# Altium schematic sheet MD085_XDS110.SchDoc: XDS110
size 431 x 279 mm; Date: Not shown in title block; ApprovedBy: Not shown in title block; CheckedBy: Not shown in title block; Author: Not shown in title block; CompanyName: Not shown in title block; DrawnBy: Keerthi Kumanan; Engineer: Not shown in title block; Organization: Not shown in title block; Address1: Not shown in title block; Address2: Not shown in title block; Address3: Not shown in title block; Address4: Not shown in title block; DocumentNumber: 2; Revision: Use project parameter SCH_Rev; SheetNumber: 2; SheetTotal: 2; PageSetup: Record=PageOptions¦CenterHorizontal=True¦CenterVertical=True¦PrintScale=1.00¦XCorrection=1.00¦YCorrection=1.00¦PrintKind=0¦BorderSize=5000000¦LeftOffset=0¦BottomOffset=0¦Orientation=2¦PaperLength=1000¦PaperWidth=1000¦Scale=100¦PaperSource=15¦PrintQuality=600¦MediaType=1¦DitherType=10¦PaperKind=Letter¦PrintScaleMode=1
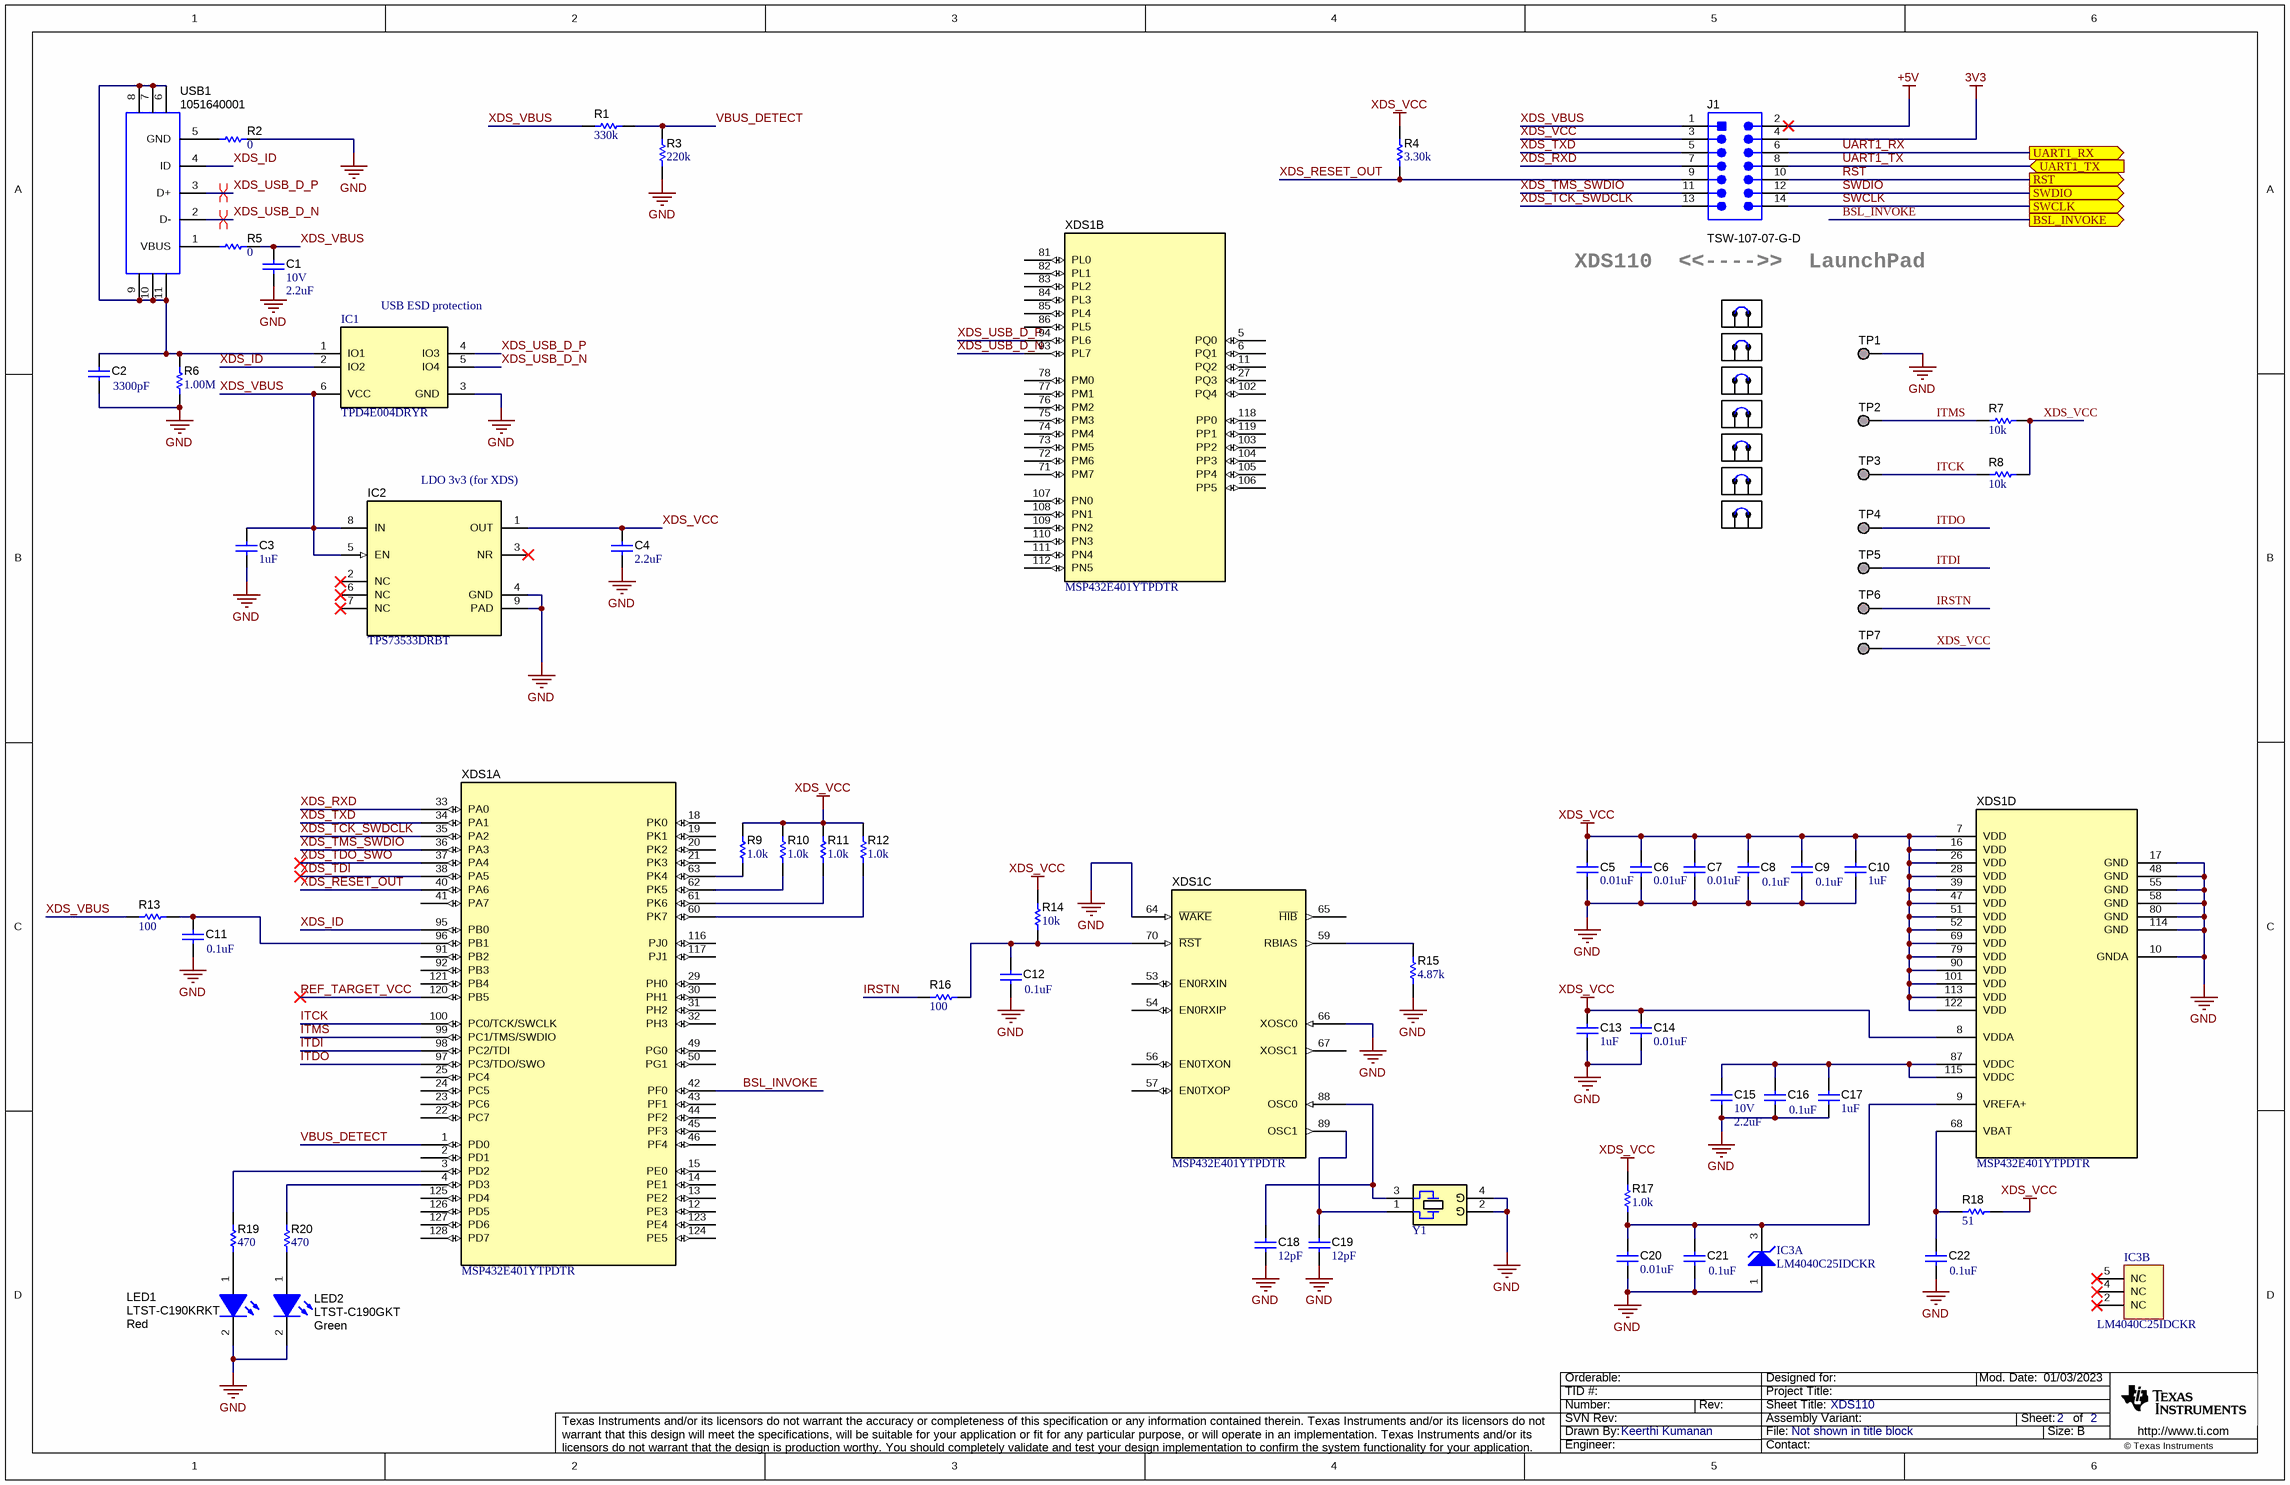
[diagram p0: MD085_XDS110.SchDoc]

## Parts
C1  VDC_V: 10V  ValueDisplayed: 2.2uF  [0603]  (hidden comment: C0603C225K8PACTU)
C2  ValueDisplayed: 3300pF  [0402]  (hidden comment: GRM155R71H332KA01D)
C3  ValueDisplayed: 1uF  [0402]  (hidden comment: C1005X5R1E105K050BC)
C4  ValueDisplayed: 2.2uF  [0402]  (hidden comment: CL05A225KQ5NNNC)
C5  ValueDisplayed: 0.01uF  [0402]  (hidden comment: GRM155R71E103KA01D)
C6  ValueDisplayed: 0.01uF  [0402]  (hidden comment: GRM155R71E103KA01D)
C7  ValueDisplayed: 0.01uF  [0402]  (hidden comment: GRM155R71E103KA01D)
C8  ValueDisplayed: 0.1uF  [0402]  (hidden comment: GRM155R70J104KA01D)
C9  ValueDisplayed: 0.1uF  [0402]  (hidden comment: GRM155R70J104KA01D)
C10  ValueDisplayed: 1uF  [0402]  (hidden comment: C1005X5R1E105K050BC)
C11  ValueDisplayed: 0.1uF  [0402]  (hidden comment: GRM155R70J104KA01D)
C12  ValueDisplayed: 0.1uF  [0402]  (hidden comment: GRM155R70J104KA01D)
C13  ValueDisplayed: 1uF  [0402]  (hidden comment: C1005X5R1E105K050BC)
C14  ValueDisplayed: 0.01uF  [0402]  (hidden comment: GRM155R71E103KA01D)
C15  VDC_V: 10V  ValueDisplayed: 2.2uF  [0603]  (hidden comment: C0603C225K8PACTU)
C16  ValueDisplayed: 0.1uF  [0402]  (hidden comment: GRM155R70J104KA01D)
C17  ValueDisplayed: 1uF  [0402]  (hidden comment: C1005X5R1E105K050BC)
C18  ValueDisplayed: 12pF  [0402]  (hidden comment: GRM1555C1H120JA01D)
C19  ValueDisplayed: 12pF  [0402]  (hidden comment: GRM1555C1H120JA01D)
C20  ValueDisplayed: 0.01uF  [0402]  (hidden comment: GRM155R71E103KA01D)
C21  ValueDisplayed: 0.1uF  [0402]  (hidden comment: GRM155R70J104KA01D)
C22  ValueDisplayed: 0.1uF  [0402]  (hidden comment: GRM155R70J104KA01D)
IC1  TPD4E004DRYR  [DRY0006A]
IC2  TPS73533DRBT  [DRB0008A]
IC3  LM4040C25IDCKR  [DCK0005A_N]  (parts A,B of 2)
J1  TSW-107-07-G-D  [TSW-107-07-X-D]
LED1  LTST-C190KRKT  value Red  [LED_LTST-C190_Red]
LED2  LTST-C190GKT  value Green  [LED_LTST-C190]
R1  ValueDisplayed: 330k  [0402]  (hidden comment: RC0402FR-07330KL)
R2  ValueDisplayed: 0  [0603]  (hidden comment: RC0603JR-070RL)
R3  ValueDisplayed: 220k  [0402]  (hidden comment: RC0402FR-07220KL)
R4  ValueDisplayed: 3.30k  [0402]  (hidden comment: ERJ-2RKF3301X)
R5  ValueDisplayed: 0  [0603]  (hidden comment: RC0603JR-070RL)
R6  ValueDisplayed: 1.00M  [0402]  (hidden comment: CRCW04021M00FKED)
R7  ValueDisplayed: 10k  [0402]  (hidden comment: CRCW040210K0JNED)
R8  ValueDisplayed: 10k  [0402]  (hidden comment: CRCW040210K0JNED)
R9  ValueDisplayed: 1.0k  [0402]  (hidden comment: CRCW04021K00JNED)
R10  ValueDisplayed: 1.0k  [0402]  (hidden comment: CRCW04021K00JNED)
R11  ValueDisplayed: 1.0k  [0402]  (hidden comment: CRCW04021K00JNED)
R12  ValueDisplayed: 1.0k  [0402]  (hidden comment: CRCW04021K00JNED)
R13  ValueDisplayed: 100  [0402]  (hidden comment: CRCW0402100RJNED)
R14  ValueDisplayed: 10k  [0402]  (hidden comment: CRCW040210K0JNED)
R15  ValueDisplayed: 4.87k  [0402]  (hidden comment: CRCW04024K87FKED)
R16  ValueDisplayed: 100  [0402]  (hidden comment: CRCW0402100RJNED)
R17  ValueDisplayed: 1.0k  [0402]  (hidden comment: CRCW04021K00JNED)
R18  ValueDisplayed: 51  [0402]  (hidden comment: CRCW040251R0JNED)
R19  ValueDisplayed: 470  [0402]  (hidden comment: CRCW0402470RJNED)
R20  ValueDisplayed: 470  [0402]  (hidden comment: CRCW0402470RJNED)
SH-J14  60900213421  [Wurth_60900213421]  (value not drawn)
SH-J15  60900213421  [Wurth_60900213421]  (value not drawn)
SH-J16  60900213421  [Wurth_60900213421]  (value not drawn)
SH-J17  60900213421  [Wurth_60900213421]  (value not drawn)
SH-J18  60900213421  [Wurth_60900213421]  (value not drawn)
SH-J19  60900213421  [Wurth_60900213421]  (value not drawn)
SH-J20  60900213421  [Wurth_60900213421]  (value not drawn)
TP1  TESTPOINT  [TP_SM_1MM]  (value not drawn)  (no BOM)
TP2  TESTPOINT  [TP_SM_1MM]  (value not drawn)  (no BOM)
TP3  TESTPOINT  [TP_SM_1MM]  (value not drawn)  (no BOM)
TP4  TESTPOINT  [TP_SM_1MM]  (value not drawn)  (no BOM)
TP5  TESTPOINT  [TP_SM_1MM]  (value not drawn)  (no BOM)
TP6  TESTPOINT  [TP_SM_1MM]  (value not drawn)  (no BOM)
TP7  TESTPOINT  [TP_SM_1MM]  (value not drawn)  (no BOM)
USB1  1051640001  [Molex_1051640001]
XDS1  MSP432E401YTPDTR  [PDT0128A]  (parts A,B,C,D of 4)
Y1  NX3225GA-16.000M-STD-CRG-1  [NDK_NX3225GA]  (value not drawn)

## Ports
BSL_INVOKE (out), RST (out), SWCLK (out), SWDIO (out), UART1_RX (out), UART1_TX (in)

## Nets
3V3: J1.4
+5V: J1.2
GND: C1.2 C2.2 C3.2 C4.2 C5.2 C6.2 C7.2 C8.2 C9.2 C10.2 C11.2 C12.2 C13.2 C14.2 C15.2 C16.2 C17.2 C18.2 C19.2 C20.2 C21.2 C22.2 IC1.3(GND) IC2.4(GND) IC2.9(PAD) IC3.1(ANODE) LED1.2(K) LED2.2(K) R2.2 R3.1 R6.1 R15.1 TP1.1 XDS1.10(GNDA) XDS1.17(GND) XDS1.48(GND) XDS1.55(GND) XDS1.58(GND) XDS1.64(~{WAKE}) XDS1.66(XOSC0) XDS1.80(GND) XDS1.114(GND) Y1.2(GND) Y1.4(GND)
XDS_VCC: C4.1 C5.1 C6.1 C7.1 C8.1 C9.1 C10.1 C13.1 C14.1 IC2.1(OUT) J1.3 R4.2 R7.1 R8.1 R9.2 R10.2 R11.2 R12.2 R14.2 R17.2 R18.2 TP7.1 XDS1.7(VDD) XDS1.8(VDDA) XDS1.16(VDD) XDS1.26(VDD) XDS1.28(VDD) XDS1.39(VDD) XDS1.47(VDD) XDS1.51(VDD) XDS1.52(VDD) XDS1.69(VDD) XDS1.79(VDD) XDS1.90(VDD) XDS1.101(VDD) XDS1.113(VDD) XDS1.122(VDD)
BSL_INVOKE: XDS1.42(PF0) ; port BSL_INVOKE
IRSTN: R16.1 TP6.1
ITCK: R8.2 TP3.1 XDS1.100(PC0/TCK/SWCLK)
ITDI: TP5.1 XDS1.98(PC2/TDI)
ITDO: TP4.1 XDS1.97(PC3/TDO/SWO)
ITMS: R7.2 TP2.1 XDS1.99(PC1/TMS/SWDIO)
REF_TARGET_VCC: XDS1.120(PB5)
RST: J1.10 ; port RST
SWCLK: J1.14 ; port SWCLK
SWDIO: J1.12 ; port SWDIO
UART1_RX: J1.6 ; port UART1_RX
UART1_TX: J1.8 ; port UART1_TX
VBUS_DETECT: R1.2 R3.2 XDS1.1(PD0)
XDS_ID: IC1.2(IO2) USB1.4(ID) XDS1.95(PB0)
XDS_RESET_OUT: J1.9 R4.1 XDS1.40(PA6)
XDS_RXD: J1.7 XDS1.33(PA0)
XDS_TCK_SWDCLK: J1.13 XDS1.35(PA2)
XDS_TDI: XDS1.38(PA5)
XDS_TDO_SWO: XDS1.37(PA4)
XDS_TMS_SWDIO: J1.11 XDS1.36(PA3)
XDS_TXD: J1.5 XDS1.34(PA1)
XDS_USB_D_N: IC1.5(IO4) USB1.2(D-) XDS1.93(PL7)
XDS_USB_D_P: IC1.4(IO3) USB1.3(D+) XDS1.94(PL6)
XDS_VBUS: C1.1 C3.1 IC1.6(VCC) IC2.5(EN) IC2.8(IN) J1.1 R1.1 R5.2 R13.1
NetC2_1: C2.1 IC1.1(IO1) R6.2 USB1.6 USB1.7 USB1.8 USB1.9 USB1.10 USB1.11
NetC11_1: C11.1 R13.2 XDS1.96(PB1)
NetC12_1: C12.1 R14.1 R16.2 XDS1.70(~{RST})
NetC15_1: C15.1 C16.1 C17.1 XDS1.87(VDDC) XDS1.115(VDDC)
NetC18_1: C18.1 XDS1.88(OSC0) Y1.3
NetC19_1: C19.1 XDS1.89(OSC1) Y1.1
NetC20_1: C20.1 C21.1 IC3.3(CATHODE) R17.1 XDS1.9(VREFA+)
NetC22_1: C22.1 R18.1 XDS1.68(VBAT)
NetLED1_1: LED1.1(A) R19.1
NetLED2_1: LED2.1(A) R20.1
NetR2_1: R2.1 USB1.5(GND)
NetR5_1: R5.1 USB1.1(VBUS)
NetR9_1: R9.1 XDS1.63(PK4)
NetR10_1: R10.1 XDS1.62(PK5)
NetR11_1: R11.1 XDS1.61(PK6)
NetR12_1: R12.1 XDS1.60(PK7)
NetR15_2: R15.2 XDS1.59(RBIAS)
NetR19_2: R19.2 XDS1.3(PD2)
NetR20_2: R20.2 XDS1.4(PD3)

Not connected (* = marked no-connect by the designer): IC2 2(NC)* 3(NR)* 6(NC)* 7(NC)*; IC3 2(NC)* 4(NC)* 5(NC)*; XDS1 2(PD1) 5(PQ0) 6(PQ1) 11(PQ2) 12(PE3) 13(PE2) 14(PE1) 15(PE0) 18(PK0) 19(PK1) 20(PK2) 21(PK3) 22(PC7) 23(PC6) 24(PC5) 25(PC4) 27(PQ3) 29(PH0) 30(PH1) 31(PH2) 32(PH3) 41(PA7) 43(PF1) 44(PF2) 45(PF3) 46(PF4) 49(PG0) 50(PG1) 53(EN0RXIN) 54(EN0RXIP) 56(EN0TXON) 57(EN0TXOP) 65(~{HIB}) 67(XOSC1) 71(PM7) 72(PM6) 73(PM5) 74(PM4) 75(PM3) 76(PM2) 77(PM1) 78(PM0) 81(PL0) 82(PL1) 83(PL2) 84(PL3) 85(PL4) 86(PL5) 91(PB2) 92(PB3) 102(PQ4) 103(PP2) 104(PP3) 105(PP4) 106(PP5) 107(PN0) 108(PN1) 109(PN2) 110(PN3) 111(PN4) 112(PN5) 116(PJ0) 117(PJ1) 118(PP0) 119(PP1) 121(PB4) 123(PE4) 124(PE5) 125(PD4) 126(PD5) 127(PD6) 128(PD7)

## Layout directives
differential pair: XDS_USB_D_N, XDS_USB_D_P

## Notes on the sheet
- XDS110  <<---->>  LaunchPad
- (near IC1) USB ESD protection
- (near IC2) LDO 3v3 (for XDS)

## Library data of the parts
C1 C15 = CMP-0006906-5: CAP, CERM, 2.2 uF, 10 V, +/- 10%, X5R, 0603; Manufacturer: Kemet; TaMin_C: -55°C; Polarized: N; SizeAreaWB_mm2: 4.68; Value1: Unknown; U/M: EA; Value: 2.2uF; TaMax_C: 85°C; SizeZ_mm: 1; SizeX_mm: 1.6; SizeY_mm: 0.8; SizeArea_mm2: 1.28; Cap_F: 2.2µF; AEC Category: Q200
C2 = CMP-0006688-2: CAP, CERM, 3300 pF, 50 V, +/- 10%, X7R, 0402; Manufacturer: MuRata; TaMin_C: -55°C; Polarized: N; SizeAreaWB_mm2: 3; Value1: Unknown; U/M: EA; Value: 3300pF; TaMax_C: 125°C; SizeZ_mm: 0.6; SizeX_mm: 1; SizeY_mm: 0.5; Value2: 50V; Cap_F: 3.3nF; AEC Category: Q200
C3 C10 C13 C17 = CMP-0006276-2: CAP, CERM, 1 uF, 25 V, +/- 10%, X5R, 0402; Manufacturer: TDK; TaMin_C: -55°C; Polarized: N; SizeAreaWB_mm2: 3; Value1: Unknown; U/M: EA; Value: 1uF; TaMax_C: 80°C; SizeZ_mm: 0.6; SizeX_mm: 1; SizeY_mm: 0.5; Value2: 25V; Cap_F: 1µF; AEC Category: Q200
C4 = CMP-0006341-2: CAP, CERM, 2.2 uF, 6.3 V, +/- 10%, X5R, 0402; Manufacturer: Samsung; TaMin_C: -55°C; Polarized: N; SizeAreaWB_mm2: 3; Value1: Unknown; U/M: EA; Value: 2.2uF; TaMax_C: 85°C; SizeZ_mm: 0.6; SizeX_mm: 1; SizeY_mm: 0.5; Value2: 6.3V; Cap_F: 2.2µF; AEC Category: Q200
C5-C7 C14 C20 = CMP-0006658-2: CAP, CERM, 0.01 uF, 25 V, +/- 10%, X7R, 0402; Manufacturer: MuRata; TaMin_C: -55°C; Polarized: N; SizeAreaWB_mm2: 3; Value1: Unknown; U/M: EA; Value: 0.01uF; TaMax_C: 125°C; SizeZ_mm: 0.6; SizeX_mm: 1; SizeY_mm: 0.5; Value2: 25V; Cap_F: 10nF; AEC Category: Q200
C8 C9 C11 C12 C16 C21 C22 = CMP-0006623-2: CAP, CERM, 0.1 uF, 6.3 V, +/- 10%, X7R, 0402; Manufacturer: MuRata; TaMin_C: -55°C; Polarized: N; SizeAreaWB_mm2: 3; Value1: Unknown; U/M: EA; Value: 0.1uF; TaMax_C: 125°C; SizeZ_mm: 0.6; SizeX_mm: 1; SizeY_mm: 0.5; Value2: 6.3V; Cap_F: 100nF; AEC Category: Q200
C18 C19 = CMP-0006415-2: CAP, CERM, 12 pF, 50 V, +/- 5%, C0G/NP0, 0402; Manufacturer: MuRata; TaMin_C: -55°C; Polarized: N; SizeAreaWB_mm2: 3; Value1: Unknown; U/M: EA; Value: 12pF; TaMax_C: 125°C; SizeZ_mm: 0.6; SizeX_mm: 1; SizeY_mm: 0.5; Value2: 50V; AEC Category: Q200
IC1 = CMP-0043115-3: 4-Channel ESD Protection Array for High-Speed Data Interfaces, DRY0006A (USON-6); Manufacturer: Texas Instruments; IO Leakage Current(nA): 1; USB High Speed: TRUE; IO Capacitance(Typ)(pF): 1.6; Eco-Plan: Green (RoHS & no Sb/Br); IEC 61000-4-2 Contact(+/- kV): 8; Breakdown Voltage(Min)(V): 6; IEC 61000-4-2 Air-Gap(+/- kV): 12; AEC Category: Q200; AEC Qualified: N; CompType: IC; Rating: Catalog; SizeArea_mm2: 1.45; SizeAreaWB_mm2: 4.9; SizeX_mm: 1.0; SizeZ_mm: 0.6
IC2 = CMP-0036329-3: 500mA, Adjustable, Low Quiescent Current, Low-Noise, High-PSRR, Single-Output LDO Regulator, DRB0008A (VSON-8); Manufacturer: Texas Instruments; AEC Category: Q200; Vout Adj(Max)(V): 3.3; Vdo(Typ)(mV): 280; SizeY_mm: 3.0; Vin(Max)(V): 6.5; Accuracy(%): 2; Vin(Min)(V): 2.7; SizeAreaWB_mm2: 16.0; SizeZ_mm: 1.0; AEC Qualified: N; SizeArea_mm2: 9.0; Iout(Max)(A): 0.5; Rating: Catalog; Iq(Typ)(mA): 0.04; CompType: IC
IC3 = CMP-0032790-2: Precision Micropower Shunt Voltage Reference, 0.5% accuracy, 2.5 V, 15 ppm / degC, 15 mA, -40 to 85 degC, 5-pin SC70 (DCK), Green (RoHS & no Sb/Br); Manufacturer: Texas Instruments; Min Iz for Regulation(uA): 75; Temp Coeff(Max)(ppm/ degree C): 100; VO(V): 2.5; Temp Coeff(Typ)(ppm/ degree C): 15; Rating: Catalog; Initial Accuracy @ 25/deg C(%): 0.5; AEC Category: Q200; AEC Qualified: N; CompType: IC; SizeAreaWB_mm2: 9.3; SizeArea_mm2: 4.2; SizeX_mm: 2.1; SizeY_mm: 2.0; SizeZ_mm: 1.1
J1 = CMP-0075415-2: Header, 100mil, 7x2, Gold, TH; Manufacturer: Samtec; Green_Lifecycle: Active; Green_REACh: Passed; Cert_CSA: Y; Cert_CULUS: N; Current_A: 6.3A; Gender: Male; Pitch_mm: 2.54; Row_Count: 2; Voltage_V: 550V
LED1 = CMP-0078131-2: LED, Red, SMD; Manufacturer: Lite-On; Type: AlInGaP; Ir_A: 10µA; Angle: 130; Power_TotalModule: 62.5mW; Value2: 2V; Green_Lifecycle: Not Set; Io_A: 20mA; Value1: .0625W; Green_REACh: Incomplete; Vr_V: 5V
LED2 = CMP-0002827-3: LED, Green, SMD; Manufacturer: Lite-On; Power_TotalModule: 100mW; Value2: 2.1V; Io_A: 20mA; Value1: 0.1W
R1 = CMP-0026731-1: RES, 330 k, 1%, 0.0625 W, 0402; Manufacturer: Yageo America; Power_W: 62.5mW; TempCo: 100 ppm/C; U/M: EA; Value: 330k; SizeX_mm: 1; SizeY_mm: 0.5; SizeZ_mm: 0.6; AEC Qualified: N; VDC_V: 50V; AEC Category: Q200
R2 R5 = CMP-0025885-5: RES, 0, 5%, 0.1 W, 0603; Manufacturer: Yageo; Power_W: 100mW; TempCo: 200 ppm/C; Value_Code: 0000; Value: 0; EIA_Code: E24; SizeX_mm: 1.6; SizeZ_mm: 1; Value2: 0.1W; SizeArea_mm2: 1.28; AEC Qualified: N; VDC_V: 75V; AEC Category: Q200; SizeY_mm: 0.8; SizeAreaWB_mm2: 4.68
R3 = CMP-0026728-1: RES, 220 k, 1%, 0.0625 W, 0402; Manufacturer: Yageo America; Power_W: 62.5mW; TempCo: 100 ppm/C; U/M: EA; Value: 220k; SizeX_mm: 1; SizeY_mm: 0.5; SizeZ_mm: 0.6; AEC Qualified: N; VDC_V: 50V; AEC Category: Q200
R4 = CMP-0026695-1: RES, 3.30 k, 1%, 0.1 W, AEC-Q200 Grade 0, 0402; Manufacturer: Panasonic; Power_W: 100mW; TempCo: 100 ppm/C; Value_Code: 3k30; U/M: EA; Value: 3.30k; Res_ohm: 3.3k; SizeX_mm: 1; SizeY_mm: 0.5; SizeZ_mm: 0.6; Value2: 0.1W; AEC Qualified: Y; VDC_V: 50V; AEC Grade: 0; AEC Category: Q200
R6 = CMP-0026100-2: RES, 1.00 M, 1%, 0.063 W, AEC-Q200 Grade 0, 0402; Manufacturer: Vishay-Dale; Power_W: 63mW; TempCo: 100 ppm/C; Value_Code: 1M00; Value: 1.00Meg; EIA_Code: E96; Res_ohm: 1M; SizeX_mm: 1; SizeY_mm: 0.5; SizeZ_mm: 0.6; Value2: 0.063W; AEC Qualified: Y; VDC_V: 50V; AEC Category: Q200; AEC Grade: 0
R7 R8 R14 = CMP-0026825-5: RES, 10 k, 5%, 0.063 W, AEC-Q200 Grade 0, 0402; Manufacturer: Vishay-Dale; Power_W: 63mW; TempCo: 200 ppm/C; Value_Code: 10k0; Value: 10k; EIA_Code: E24; SizeX_mm: 1; SizeY_mm: 0.5; SizeZ_mm: 0.6; Value2: 0.063W; AEC Qualified: Y; VDC_V: 50V; AEC Category: Q200; AEC Grade: 0
R9-R12 R17 = CMP-0026852-3: RES, 1.0 k, 5%, 0.063 W, AEC-Q200 Grade 0, 0402; Manufacturer: Vishay-Dale; Power_W: 63mW; TempCo: 200 ppm/C; Value_Code: 1k00; Value: 1.0k; EIA_Code: E24; Res_ohm: 1k; SizeX_mm: 1; SizeY_mm: 0.5; SizeZ_mm: 0.6; Value2: 0.063W; AEC Qualified: Y; VDC_V: 50V; AEC Category: Q200; AEC Grade: 0
R13 R16 = CMP-0026824-3: RES, 100, 5%, 0.063 W, AEC-Q200 Grade 0, 0402; Manufacturer: Vishay-Dale; Power_W: 63mW; TempCo: 200 ppm/C; Value_Code: 100R; Value: 100; EIA_Code: E24; SizeX_mm: 1; SizeY_mm: 0.5; SizeZ_mm: 0.6; Value2: 0.063W; AEC Qualified: Y; VDC_V: 50V; AEC Category: Q200; AEC Grade: 0
R15 = CMP-0026413-2: RES, 4.87 k, 1%, 0.063 W, AEC-Q200 Grade 0, 0402; Manufacturer: Vishay-Dale; Power_W: 63mW; TempCo: 100 ppm/C; Value_Code: 4k87; Value: 4.87k; EIA_Code: E96; SizeX_mm: 1; SizeY_mm: 0.5; SizeZ_mm: 0.6; Value2: 0.063W; AEC Qualified: Y; VDC_V: 50V; AEC Category: Q200; AEC Grade: 0
R18 = CMP-0026946-3: RES, 51, 5%, 0.063 W, AEC-Q200 Grade 0, 0402; Manufacturer: Vishay-Dale; Power_W: 63mW; TempCo: 200 ppm/C; Value_Code: 51R0; Value: 51; EIA_Code: E24; SizeX_mm: 1; SizeY_mm: 0.5; SizeZ_mm: 0.6; Value2: 0.063W; AEC Qualified: Y; VDC_V: 50V; AEC Category: Q200; AEC Grade: 0
R19 R20 = CMP-0026934-3: RES, 470, 5%, 0.063 W, AEC-Q200 Grade 0, 0402; Manufacturer: Vishay-Dale; Power_W: 63mW; TempCo: 200 ppm/C; Value_Code: 470R; Value: 470; EIA_Code: E24; SizeX_mm: 1; SizeY_mm: 0.5; SizeZ_mm: 0.6; Value2: 0.063W; AEC Qualified: Y; VDC_V: 50V; AEC Category: Q200; AEC Grade: 0
SH-J14-SH-J20 = CMP-0003761-2: Shunt, 2.54mm, Gold, Black; Manufacturer: Wurth Elektronik
TP1-TP7 = CMP-0003825-1: 1mm Test Point, SMT; Manufacturer: Any
USB1 = CMP-0055311-1: Receptacle, USB 2.0, Micro B, 5 Position, R/A, SMT; Manufacturer: Molex; CNHeader: FALSE; Current_A: 1.8A; Gender: Female; Voltage_V: 30V; Pitch_mm: 0.65; ContactFinish: Gold; CT: TRUE; Cert_UL: Y
XDS1 = CMP-0077954-1: MSP432E401YTPDT, PDT0128A (TQFP-128); Alternate Manufacturer: Texas Instruments; SizeAreaWB_mm2: 324; SizeZ_mm: 1.2; SizeX_mm: 16; SizeArea_mm2: 256; CompType: IC; AEC Qualified: N; AEC Category: Q200
Y1 = CMP-0004635-3: Crystal, 16 MHz, 8pF, SMD; Manufacturer: NDK; TaMax_C: 70°C; TaMin_C: -10°C; Frequency Stability: +/-30ppm; Frequency_Fixed: 16MHz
